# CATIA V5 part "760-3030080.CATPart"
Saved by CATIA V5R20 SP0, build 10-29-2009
Part number: 760-3030080
Source: Unknown
Property "A": "34.000"
Property "ARTICLENO": "760-3030080"
Property "BOMINFO": "760-3030080"
Property "CODE": "760-3030080"
Property "K": "45.000"
Property "L": "90.000"
Property "LINA": "760-3030080"
Property "NB": "760-3030080"
Property "NBSYN": "$CODE."
Property "NN": "760"
Property "NT": "Key"
Property "SUPPLIER": "CF"
Bounding box of the stored display mesh (mm): x -45 to 45, y 0 to 34, z -17 to 17
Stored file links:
  C:\Users\Utente\Desktop\3D files 760\760-3030080.CATPart
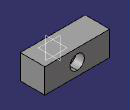
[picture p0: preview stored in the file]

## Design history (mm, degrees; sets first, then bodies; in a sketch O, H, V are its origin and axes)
Body1 "Geometry.1" (main body)
  Solid1 "760-3030080.catpart": solid without history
